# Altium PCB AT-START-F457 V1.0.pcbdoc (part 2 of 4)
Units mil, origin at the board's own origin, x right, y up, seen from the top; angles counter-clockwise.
Board outline 11593.57 x 3554 mil, 2 copper layers (Top Layer, Bottom Layer); 196 components, 231 nets, 905 pads, 932 vias.
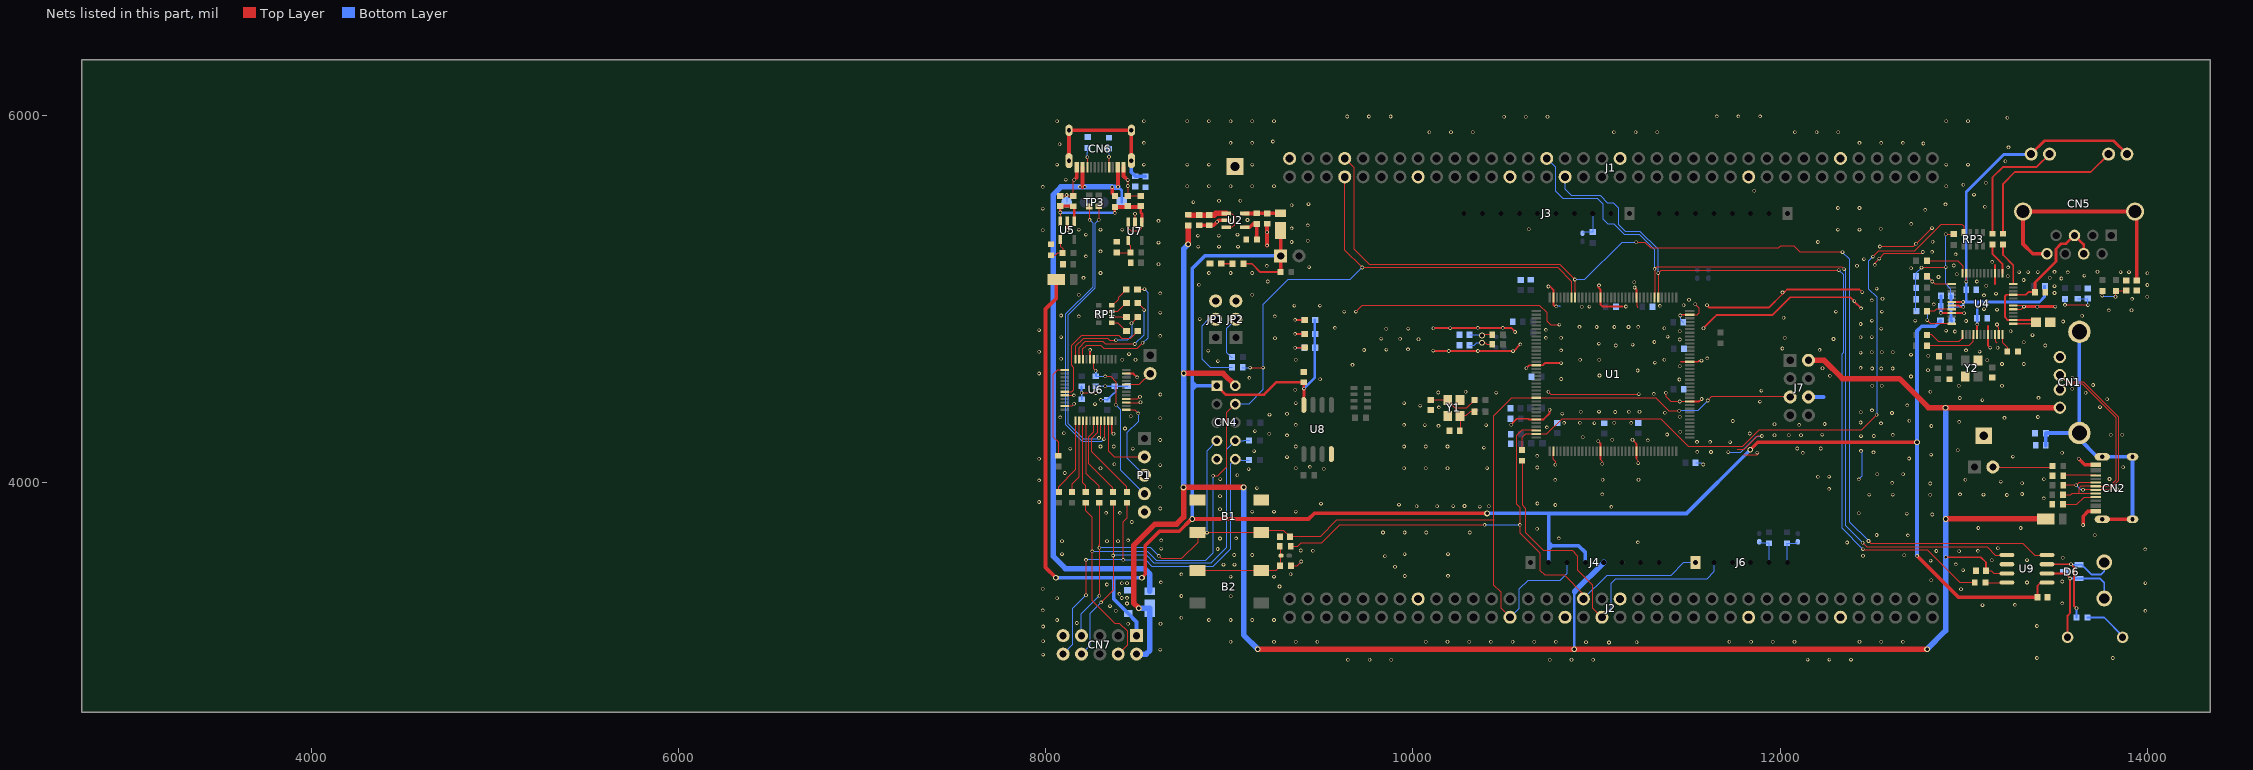
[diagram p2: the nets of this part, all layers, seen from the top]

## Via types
v1: diameter 19.7, hole 11.8, Top Layer to Bottom Layer, 489 vias
v2: diameter 19.68, hole 11.81, Top Layer to Bottom Layer, 425 vias
v3: diameter 31.5, hole 19.68, Top Layer to Bottom Layer, 18 vias

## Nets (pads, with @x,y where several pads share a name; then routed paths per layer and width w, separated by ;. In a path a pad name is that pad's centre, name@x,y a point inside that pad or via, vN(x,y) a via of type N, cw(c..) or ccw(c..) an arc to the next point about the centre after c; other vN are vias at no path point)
3V3: C13.1 C53.2 CN4.1 CN7.1 D1.1 D4.1 D5.1 J4.2 J4.4 JP3.1 L3.1 R10.1 R17.1 R26.1 R27.1 R28.1 U8.8 U9.5 | length 13515.4
  Top Layer w10: R10.1@9075.76,5191.98 9124.16,5191.98 9169.26,5146.98 R17.1@9280.76,5146.98 ; C53.2@13402.01,3375.61 13402.01,3438.05 13419.57,3455.61 U9.5@13453.72,3455.61
  Top Layer w15: CN4.1@8933.26,4527.98 8980.46,4480.48 9189.26,4479.18 9257.66,4547.38 9406.16,4547.38 9406.16,4512.98 9406.76,4512.38 U8.8@9406.16,4423.68
  Top Layer w20: v3(8056.02,3482.17) 7999.57,3538.62 7999.57,4945.41 8058.76,5004.61 D5.1@8058.76,5091.44 ; D5.1@8058.76,5107.05 D5.1@8058.76,5091.44 ; D5.1@8078.86,5111.53 D5.1@8058.76,5091.44 ; v3(8524.32,3482.61) 8542.32,3500.61 8542.32,3657.37 8620.57,3735.61 8728.41,3735.61 8794.76,3801.97 v3(8798.21,3801.97) 9432.21,3801.97 9462.85,3832.61 v3(10404.61,3832.61) ; D1.1@9280.21,5373.23 JP3.1@9280.21,5234.97 9280.16,5147.48 R17.1@9280.76,5146.98 ; v3(11837.81,4179.57) 11878.59,4220.35 v3(12745.71,4220.35) ; v2(12746.45,3600.9) 12971.74,3375.61 C53.2@13402.01,3375.61
  Bottom Layer w15: v2@9406.76,4512.38 9465.36,4571.08 R28.1@9465.36,4886.28
  Bottom Layer w20: v3(8056.02,3482.17) 8056.47,3482.61 8362.66,3482.61 ; CN7.1@8495.46,3166.58 8495.46,3241.74 D4.1@8449.57,3287.62 8370.57,3366.62 8370.57,3474.71 8362.66,3482.61 ; v3(8524.32,3482.61) 8362.66,3482.61 ; v3@8798.26,3801.98 8798.26,4505.87 ; CN4.1@8933.26,4527.98 8817.56,4528.58 ; JP3.1@9280.21,5234.97 8867.26,5234.98 8798.26,5165.98 8798.26,4547.88 ; v3(10404.61,3832.61) 10739.23,3832.61 10739.86,3831.98 ; J4.2@10739.86,3565.98 10739.86,3638.78 ; J4.4@10939.86,3565.98 10939.86,3619.38 10902.26,3656.98 10757.56,3656.98 ; v3(11837.81,4179.57) 11490.22,3831.98 10739.86,3831.98 ; v3(12745.71,4220.35) 12745.67,3601.69 v2(12746.45,3600.9) ; v3(12745.71,4220.35) 12745.67,4825.58 12771.76,4851.67 12844.53,4851.67 L3.1@12873.89,4881.03 ; 8798.26,4505.87 8817.56,4525.17 8817.56,4528.58 ; 8798.26,4505.87 8798.26,4547.88 ; 8798.26,4547.88 8817.56,4528.58 ; 10739.86,3638.78 10757.56,3656.98 ; 10739.86,3638.78 10739.86,3674.68 ; 10739.86,3674.68 10757.56,3656.98 ; 10739.86,3674.68 10739.86,3831.98
  other v2: 9406.72,4512.39
3V3_EMAC: C41.1 C42.1 C43.1 C44.1 CN5.9 CN5.12 L3.2 R66.1 R67.1 R68.1 R69.1 R72.2 R75.2 U4.23 U4.30 U4.31 U4.41 | length 3491.9
  Top Layer w6: v2(12770.45,5171.33) 12900.09,5171.33 v2(12902.68,5173.92) ; v2(12901.89,5353.19) 12944.44,5353.2 R68.1@12946.16,5351.48
  Top Layer w10: U4.30@12934.89,4983.81 12934.95,4983.87 v2(12996.99,4983.87) ; U4.31@12934.89,4964.13 12974.3,4964.13 12980.93,4957.51 v2(12997.27,4957.51) ; v2@13013.66,5094.98 U4.23@13013.66,5141.28 ; U4.41@13072.66,4806.68 13072.66,4860.98 v2@13073.76,4861.98
  Top Layer w15: CN5.12@13367.43,5789.39 13439.93,5861.97 13816.5,5861.97 CN5.9@13889.04,5789.42
  Bottom Layer w5.98: v2(12902.68,5173.92) 12902.68,5082.77 12930.86,5054.59 C42.1@12930.86,5017.89
  Bottom Layer w6: R72.2@12739.45,5122.7 12739.45,4937.91 R69.1@12742.21,4935.15 ; R72.2@12739.45,5124.27 12739.45,5140.34 v2(12770.45,5171.33) ; v2@12901.1,5352.36 12901.1,5175.49 v2(12902.68,5173.92)
  Bottom Layer w10: v2@13013.66,5094.98 v2@13013.76,5094.88
  Bottom Layer w15: C41.1@12930.22,4960.31 C41.1@12930.86,4960.31 ; C42.1@12930.86,5017.89 C41.1@12930.86,4960.31 ; L3.2@12934.52,4881.03 12930.86,4884.69 C41.1@12930.86,4960.31 ; v2(12997.27,4957.51) v2@12996.99,4957.78 ; v2@13073.76,4861.98 13073.76,4982.48 13072.26,4983.98 ; CN5.12@13367.43,5789.39 13364.96,5786.98 13218.26,5786.98 13013.76,5582.48 13013.76,5094.88 13013.76,4985.56 13015.44,4983.87 ; R75.2@13440.76,5069.98 13440.76,5012.48 13412.26,4983.98 13072.26,4983.98 ; C41.1@12930.86,4960.31 12994.46,4960.31 v2@12996.99,4957.78 ; v2@12996.99,4957.78 v2(12996.99,4983.87) 13015.44,4983.87 ; 13015.44,4983.87 13072.15,4983.87 13072.26,4983.98
  other v2: 13073.71,4861.97 13013.63,5094.97
5V: C52.2 CN1.1 CN4.2 CN7.2 D2.1 D3.1 F1.1 J4.5 J7.2 U9.3 | length 12164.3
  Top Layer w5.98: v3@12900.9,4408.11 v3(12901.18,4408.39) ; C52.2@13122.13,3520.61 13149.57,3520.61 13164.57,3505.61 U9.3@13235.42,3505.61
  Top Layer w10: v2(12902,3593.82) 13093.51,3593.82 13122.13,3565.2 C52.2@13122.13,3520.61
  Top Layer w30: v3(8507.66,3316.18) 8479.57,3344.27 8479.57,3658.61 8595.57,3774.61 8713.57,3774.61 8751.21,3812.25 v3(8751.21,3973.97) v3(9078.21,3973.97) ; v3(8752.21,4594.97) 8966.24,4594.97 CN4.2@9033.23,4527.98 ; v3@8776.26,5297.98 F1.1@8776.26,5399.98 ; v3(9155.76,3092.78) v3(10879.34,3092.78) v3(12800.59,3092.78) ; J7.2@12154.86,4666.58 12239.6,4666.58 12339.57,4566.61 12649.57,4566.61 12808.07,4408.11 12900.9,4408.11 CN1.1@13523.5,4408.11 ; v3(12902.7,3802.27) 12903.39,3802.96 D2.1@13445.99,3802.96
  Bottom Layer w15: v3(10879.34,3092.78) 10879.26,3092.87 10879.26,3404.98 10881.26,3406.98
  Bottom Layer w30: CN7.2@8495.46,3066.58 8547.53,3066.58 8567.57,3086.61 D3.1@8567.57,3315.86 8507.97,3315.86 v3(8507.66,3316.18) ; v3(8751.21,3973.97) 8751.21,5272.97 v3(8776.21,5297.97) ; v3@9078.26,3973.98 9078.26,3170.38 v3(9155.76,3092.78) ; 10881.26,3406.98 J4.5@11039.86,3565.98 ; v3(12800.59,3092.78) 12902.03,3194.21 v2(12902,3593.82) ; v3(12901.18,4408.39) 12902,4407.58 v2(12902,3593.82)
$2N452: C1.2 R1.1 Y1.1 | length 279.2
  Top Layer w6: C1.2@10097.57,4450.17 10097.82,4449.92 Y1.1@10190.1,4449.92 10190.1,4445.99 10231.48,4404.61 10291.04,4404.61 10335.91,4449.48 R1.1@10335.91,4450.61
$2N453: C2.2 R3.1 Y1.3 | length 170
  Top Layer w6: C2.2@10255.13,4282.61 10257.03,4284.52 Y1.3@10257.03,4363.3 10288.26,4363.3 10311.57,4386.61 R3.1@10335.91,4386.61
$2N511: C3.2 R5.1 X1.1 | length 127.4
  Top Layer w5.98: X1.1@10376.57,4801.3 10381.19,4805.92 R5.1@10432.54,4805.92
  Bottom Layer w5.98: C3.2@10308.62,4805.16 10372.7,4805.16 X1.1@10376.57,4801.3
$2N512: C4.2 R6.1 X1.2 | length 132.6
  Top Layer w5.98: X1.2@10376.57,4761.93 10394.24,4761.93 10402.99,4753.19 R6.1@10432.54,4753.19
  Bottom Layer w5.98: C4.2@10308.63,4749.61 10335.57,4749.61 10347.88,4761.93 X1.2@10376.57,4761.93
$2N701: JP1.2 R13.1 | length 455.4
  Bottom Layer w6: JP1.2@8926.26,4889.98 8887.16,4889.98 8850.26,4852.98 8850.26,4674.98 8897.16,4627.98 R13.1@9016.76,4627.98
$2N702: JP2.2 R14.1 | length 244.9
  Bottom Layer w6: R14.1@9017.76,4683.98 9011.76,4683.98 8984.26,4711.48 8984.26,4837.98 JP2.2@9036.26,4889.98
$3N58: C5.1 C6.1 F1.2 U2.1 U2.3 | length 369.5
  Top Layer w6: U2.1@8971.16,5465.98 9014.56,5464.58 9026.26,5452.98 9026.26,5402.98 9014.16,5390.98 U2.3@8984.26,5390.98
  Top Layer w30: F1.2@8776.26,5459.28 8778.36,5457.08 8836.21,5457.08 8891.21,5457.08 8917.86,5457.08 8926.66,5465.98 8971.16,5465.98 U2.1@8984.26,5465.98
$3N81: R15.1 R16.1 U2.4 | length 160.8
  Top Layer w20: U2.4@9084.26,5390.98 9111.16,5390.98 9130.76,5410.48 9150.26,5410.48 9150.26,5324.48 R15.1@9149.66,5323.98
$3N82: C7.1 D1.2 R16.2 U2.5 | length 196.6
  Top Layer w20: U2.5@9084.26,5465.98 9114.76,5465.98 9115.16,5465.48 9150.16,5465.48 9151.46,5466.68 D1.2@9280.21,5466.73
$3N119: LED1.1 R10.2 | length 64.5
  Top Layer w10: LED1.1@8956.26,5192.78 R10.2@9020.76,5191.98
$3N184: B2.2 B2.4 R18.2 R19.1 R20.1 | length 568
  Top Layer w6: B2.4@8828.03,3521.56 B2.2@9174.49,3521.56 9252.26,3521.58 9278.66,3547.98 9277.66,3548.98 R19.1@9277.66,3653.98
$3N504: LED2.1 R26.2 | length 104.4
  Top Layer w10: v2@9358.66,4734.58 9359.26,4735.18 LED2.1@9411.01,4735.2
  Bottom Layer w10: v2@9358.66,4734.58 9359.06,4734.98 R26.2@9410.36,4734.98
  other v2: 9358.65,4734.61
$3N505: LED3.1 R27.2 | length 104.1
  Top Layer w10: v2@9358.66,4809.98 LED3.1@9411.06,4810.18
  Bottom Layer w10: v2@9358.66,4809.98 R27.2@9410.36,4809.98
  other v2: 9358.65,4810
$3N506: LED4.1 R28.2 | length 104.1
  Top Layer w10: v2@9358.66,4886.28 LED4.1@9411.06,4886.48
  Bottom Layer w10: v2@9358.66,4886.28 R28.2@9410.36,4886.28
  other v2: 9358.65,4886.3
$3N17443: CN2.B5 R33.2 | length 177
  Top Layer w5.98: R33.2@13542.43,4038.23 13543.84,4039.63 CN2.B5@13718.81,4039.63
$3N17484: CN2.A5 R32.2 | length 193.6
  Top Layer w5.98: R32.2@13541.65,3881.81 13615.76,3881.81 13655.49,3921.53 CN2.A5@13718.81,3921.53
$3N17593: JP4.2 R34.1 | length 326.5
  Top Layer w5.98: JP4.2@13158.9,4085.21 13477.69,4085.21 R34.1@13483.11,4090.63
$3N21099: R90.2 U9.4 | length 116.2
  Top Layer w5.98: R90.2@13119.23,3455.61 U9.4@13235.42,3455.61
$3N21100: R89.1 SW1.2 | length 240.3
  Bottom Layer w10: R89.1@13674.23,3265.61 13764.57,3265.61 13865.56,3164.62 SW1.2@13865.56,3157.52
$4N269: J6.5 R56.2 R57.2 | length 163
  Bottom Layer w6: R56.2@11886.26,3678.68 11892.46,3672.48 11940.16,3672.48 J6.5@11939.86,3565.98
$4N270: J6.6 R58.2 R59.2 | length 168.5
  Bottom Layer w6: J6.6@12039.8,3565.97 12039.81,3667.56 R59.2@12037.06,3670.3 12089.36,3670.3 R58.2@12096.95,3677.89
$4N339: J3.3 R60.1 R61.2 | length 161.8
  Bottom Layer w6: R60.1@10926.16,5357.28 10926.16,5362.48 10979.26,5362.48 J3.3@10979.86,5465.98
$5N126: R62.2 U4.24 | length 246.2
  Top Layer w6: R62.2@12799.87,5209.08 12967.15,5209.08 12993.96,5182.28 U4.24@12993.96,5141.28
$5N184: R69.2 U4.36 | length 191
  Top Layer w6: v2(12801.82,4885.52) 12821.66,4865.68 U4.36@12934.89,4865.7
  Bottom Layer w6: R69.2@12801.53,4935.15 12801.82,4934.86 v2(12801.82,4885.52)
$5N285: C46.1 R76.1 R77.1 | length 250.4
  Top Layer w6: v2(13551.96,4968) 13552.87,4967.09 v2(13676.61,4967.09)
  Bottom Layer w5.98: R77.1@13621.73,5001.24 13675.18,5001.24 C46.1@13676.49,5002.55 13676.61,5002.44 v2(13676.61,4967.09)
  Bottom Layer w6: v2(13551.96,4968) 13551.96,5002.28 R76.1@13552.16,5002.48
$5N306: C47.1 R78.1 R79.1 | length 189.5
  Top Layer w6: v2(13754.72,5018.4) R78.1@13754.72,5043.84 ; v2(13826.57,5012.57) 13827,5013 13827,5043.18 13830.21,5046.39 C47.1@13884.55,5046.39
  Bottom Layer w6: v2(13754.72,5018.4) 13760.72,5012.4 13826.4,5012.4 v2(13826.57,5012.57)
$5N309: CN5.10 R80.1 | length 915.5
  Top Layer w10: R80.1@13214.26,5353.48 13214.26,5626.98 13279.26,5691.98 13691.56,5691.98 CN5.10@13789.09,5789.39
$5N310: CN5.11 R81.1 | length 672.4
  Top Layer w10: R81.1@13156.26,5353.48 13156.26,5661.98 13214.26,5719.98 13397.96,5719.98 CN5.11@13467.43,5789.39
$5N573: R74.2 U4.48 | length 103.9
  Top Layer w6: U4.48@13210.46,4806.68 13210.46,4764.93 13237.11,4738.27 R74.2@13237.11,4713.81
$6N792: LD1.1 RP1.8 | length 121.7
  Top Layer w6: RP1.8@8360.2,4965.45 8363.16,4965.45 8397.25,4999.55 8397.25,5009.62 8439.43,5051.8 LD1.1@8439.43,5052.63
$6N793: LD2.1 RP1.7 | length 98.6
  Top Layer w6: RP1.7@8360.2,4933.96 8393.82,4933.96 8438.39,4978.53 LD2.1@8440.39,4978.53
$6N794: LD3.1 RP1.6 | length 80.6
  Top Layer w6: RP1.6@8360.2,4902.46 8415.6,4902.46 8416.43,4901.63 LD3.1@8440.43,4901.63
$6N795: LD4.1 RP1.5 | length 99
  Top Layer w6: RP1.5@8360.2,4870.97 8393.05,4870.97 8438.39,4825.63 LD4.1@8440.39,4825.63
$6N16959: C15.2 C16.2 C18.2 C19.2 F2.2 U5.1 U5.3 U7.1 U7.3 | length 955.4
  Top Layer w6: v2(8079.97,5471.01) 8079.97,5424.64 U5.3@8080.56,5424.05 ; U7.3@8449.34,5418.39 8449.34,5386.85 8465.17,5371.01 8510.77,5371.01 8524.34,5384.58 U7.1@8524.34,5418.39
  Top Layer w15: v2(8079.97,5471.01) 8079.97,5504.25 8077.97,5506.25 8149.57,5506.25 C19.2@8150.37,5505.45 8155.56,5500.26 U5.1@8155.56,5424.05 ; v2(8376.76,5469.02) 8376.76,5500.59 F2.2@8377.56,5501.39 ; C16.2@8517.56,5506.49 8517.56,5471.42 8524.34,5464.65 U7.1@8524.34,5418.39
  Top Layer w20: F2.2@8377.56,5501.39 8512.46,5501.39 C16.2@8517.56,5506.49
  Bottom Layer w15: v2(8079.97,5471.01) 8081.17,5469.81 8375.97,5469.81 v2(8376.76,5469.02)
$6N17598: R43.2 R49.1 U7.4 | length 144.7
  Top Layer w6: R49.1@8387.57,5252.95 8439.57,5252.95 8440.03,5253.41 R43.2@8461.9,5253.41 8461.9,5290.28 8449.34,5302.85 U7.4@8449.34,5318.39
$6N17675: R50.2 R51.1 U5.4 | length 146.5
  Top Layer w6: R51.1@8029.57,5238.95 8052.89,5238.95 8064.98,5251.05 R50.2@8092.9,5251.05 8092.9,5275.68 8080.56,5288.02 U5.4@8080.56,5324.05
ATLINK_5V: CN6.A4B9 CN6.B4A9 D3.2 F2.1 TP3.1 | length 3362.8
  Top Layer w20: CN6.B4A9@8200.71,5717.9 8200.71,5609.88 8201.17,5609.41 ; v2(8362.76,5609.37) 8362.76,5575.52 F2.1@8377.56,5560.71 ; CN6.A4B9@8393.71,5717.9 8394.27,5717.34 v2(8394.27,5611.13)
  Bottom Layer w15: v2(8394.27,5611.13) 8414.58,5590.82 TP3.1@8414.58,5526.61
  Bottom Layer w30: v2(8394.27,5611.13) 8392.51,5609.37 v2(8362.76,5609.37) 8361.51,5610.61 v2(8213.24,5610.61) v2(8186.47,5610.61) 8083.57,5610.61 8042.25,5569.3 8042.25,3597.93 8108.3,3531.88 8537.57,3531.88 8567.57,3501.88 D3.2@8567.57,3409.36
ATLK_BOOT0: R45.1 U6.27 | length 395.7
  Top Layer w6: U6.27@8203.01,4337.98 8202.96,3998.78 8218.46,3983.38 R45.1@8218.46,3948.68
ATLK_NRST: R46.1 U6.28 | length 419.2
  Top Layer w6: U6.28@8222.69,4337.98 8222.66,4049.48 8292.46,3979.78 R46.1@8292.46,3947.68
ATLK_RX: CN4.10 CN7.10 R25.1 R48.2 | length 2281.5
  Top Layer w6: v2(8219.86,3386.38) 8219.86,3578.78 v2(8220.26,3579.18) ; v2@8425.16,3576.68 v2(8422.66,3579.18) 8422.66,3788.08 8443.66,3809.08 R48.2@8443.66,3892.68
  Bottom Layer w6: CN7.10@8095.46,3066.58 8145.96,3117.18 8145.96,3312.48 v2(8219.86,3386.38) ; v2(8220.26,3579.18) v2(8422.66,3579.18) 8545,3579.18 8579.46,3544.73 8913.43,3544.73 9007.59,3638.89 9007.59,4102.34 CN4.10@9033.23,4127.98 ; CN4.10@9061.16,4128.18 9066.16,4123.08 R25.1@9110.16,4123.08
ATLK_SWCLK: R41.1 U6.25 | length 427
  Top Layer w6: R41.1@8070.46,3949.58 8070.46,3979.08 8163.66,4072.28 U6.25@8163.66,4337.98
ATLK_SWDIO: R44.1 U6.26 | length 404.5
  Top Layer w6: R44.1@8144.46,3949.58 8144.46,3993.08 8183.36,4031.98 U6.26@8183.36,4337.98
ATLK_SWO: R52.1 U6.13 | length 530.4
  Top Layer w6: R52.1@8070.26,4142.58 8070.26,4218.73 8042.65,4246.34 8042.65,4589.69 8066.53,4613.58 U6.13@8104.58,4613.57
ATLK_TX: CN4.8 CN7.8 R24.1 R47.2 | length 2247.2
  Top Layer w6: v2(8302.46,3348.18) 8367.5,3413.22 v2(8367.5,3603.41) 8367.5,3846.62 8367.66,3846.78 R47.2@8367.66,3892.68
  Bottom Layer w6: CN7.8@8195.43,3066.63 8244,3115.2 8244,3289.72 v2(8302.46,3348.18) ; v2(8367.5,3603.41) 8368.11,3604.03 8550.15,3604.03 8592.12,3562.06 8900.43,3562.06 8985.14,3646.77 8985.14,4179.88 CN4.8@9033.23,4227.98 ; CN4.8@9033.26,4227.98 9078.86,4227.98 9080.96,4229.98 R24.1@9110.76,4229.98
AVDD18: C45.2 C48.2 CN5.4 CN5.5 U4.1 U4.2 U4.9 | length 1127.8
  Top Layer w10: U4.1@13269.53,4865.7 13384.64,4865.7 C45.2@13393.08,4874.14 13381.83,4885.39 U4.2@13269.53,4885.39 13240.46,4885.38 13225.36,4900.48 13225.36,5016.28 13232.26,5023.18 13269.56,5023.18 13337.46,5023.18 13352.26,5037.98 C48.2@13388.65,5037.97
  Top Layer w15: C48.2@13388.65,5037.97 13388.66,5090.48 13502.76,5204.58 13502.76,5273.18 13531.16,5301.58 13558.26,5301.58 13603.26,5346.48 13653.26,5296.48 CN5.4@13653.26,5246.48
BOOT0: CN4.4 CN7.4 J1.66 R13.2 R45.2 U1.138 | length 5702.5
  Top Layer w6: R45.2@8218.66,3892.68 8218.66,3846.33 8253.97,3811.01 8253.97,3355.87 8378.26,3231.58 8403.96,3231.58 8446.06,3189.58 8446.06,3117.18 CN7.4@8395.46,3066.58 ; v2(8912.21,4037.97) 8937.81,4037.97 8987.5,4087.66 8987.5,4382.24 CN4.4@9033.23,4427.98 ; v2(9113.66,4626.6) v2(9184.53,4626.6) ; J1.66@9629.16,5665.18 9629.16,5266.98 v2(9724.26,5171.98) 10789.04,5171.98 10863.86,5097.17 U1.138@10863.86,5008.28
  Bottom Layer w6: v2(8254.21,3625.97) 8554.21,3625.97 8603.22,3576.97 8870.92,3576.97 8912.21,3618.25 v2(8912.21,4037.97) ; CN4.4@9033.26,4427.98 9105.76,4428.18 9183.26,4505.68 9183.26,4968.98 9319.14,5104.86 9657.14,5104.86 v2(9724.26,5171.98) ; R13.2@9071.76,4627.98 9073.06,4626.58 v2(9113.66,4626.6)
CAN1_RX: J1.42 R90.1 U1.114 | length 4279.4
  Top Layer w5.98: v2(11336.13,5141.22) 11352.2,5157.28 v1(12319.64,5157.28) ; v2(12451.03,3638.03) 12456.31,3632.75 12804.57,3632.75 12981.7,3455.61 R90.1@13059.91,3455.61
  Top Layer w6: v2(11336.13,5141.22) 11336.08,5008.45 U1.114@11336.26,5008.28
  Bottom Layer w5.98: v1(12319.64,5157.28) 12342.85,5134.07 12342.85,4706.82 12335.71,4699.68 12335.71,3753.35 v2(12451.03,3638.03)
  Bottom Layer w6: J1.42@10829.16,5665.68 10829.16,5596.98 10864.26,5561.98 11022.26,5561.98 11062.16,5521.98 11094.26,5521.98 11122.26,5493.98 11122.26,5404.58 11160.26,5366.58 11239.56,5366.58 11336.08,5270.05 v2(11336.13,5141.22)
CAN1_STB: J1.65 U1.137 U9.8 | length 6093.1
  Top Layer w5.98: v2(11216.97,5309.63) 11264.09,5309.63 11295.07,5278.65 11993.09,5278.65 12004.09,5289.66 12073.68,5289.66 12106.14,5257.2 12338.43,5257.2 v2(12339.88,5255.76) ; v2(12481.84,3682.37) 12494.32,3669.89 13321.46,3669.89 13385.74,3605.61 U9.8@13453.72,3605.61
  Top Layer w6: J1.65@9629.16,5765.68 9680.26,5714.58 9680.26,5271.88 9766.26,5185.98 10803.15,5185.98 v2(10882.68,5106.45) 10883.56,5105.57 U1.137@10883.56,5008.28
  Bottom Layer w5.98: v2(10882.68,5106.45) 10936.81,5106.45 11139.99,5309.63 v2(11216.97,5309.63) ; v2(12339.88,5255.76) 12378.61,5217.03 12378.61,3785.6 v2(12481.84,3682.37)
CAN1_TX: J1.43 U1.115 U9.1 | length 4566.6
  Top Layer w5.98: v2(11316.43,5164.07) 11328.47,5176.1 12335.64,5176.1 v2(12348.76,5162.99) ; v2(12449.79,3672.41) 12471.81,3650.38 13128.09,3650.38 13172.86,3605.61 U9.1@13235.42,3605.61
  Top Layer w6: v2(11316.43,5164.07) 11316.38,5008.45 U1.115@11316.56,5008.28
  Bottom Layer w6: J1.43@10729.16,5765.68 10778.26,5716.58 10778.26,5585.88 10818.26,5545.98 11006.26,5545.98 11036.26,5515.98 11036.26,5433.88 11063.76,5406.38 11095.86,5406.38 11153.26,5348.98 11235.96,5348.98 11316.38,5268.55 v2(11316.43,5164.07) ; v2(12348.76,5162.99) 12356.62,5155.12 12356.62,3765.58 v2(12449.79,3672.41)
CAN_H: CN8.2 D6.1 R89.2 U9.7 | length 693.4
  Top Layer w10: U9.7@13453.72,3555.61 v2(13584.57,3555.61) 13600.4,3539.79 13600.4,3329.79 v2(13614.57,3315.61)
  Bottom Layer w10: v2(13584.57,3555.61) 13587.17,3553.01 D6.1@13628.94,3553.01 13642.17,3553.01 13694.57,3500.61 13749.57,3500.61 13765.59,3516.64 CN8.2@13765.59,3566.16 ; v2(13614.57,3315.61) 13614.57,3265.95 R89.2@13614.91,3265.61
CAN_L: CN8.1 D6.2 SW1.1 U9.6 | length 744.8
  Top Layer w10: U9.6@13453.72,3505.61 13552.17,3505.61 v2(13579.57,3478.21) 13579.57,3290.14 13565.56,3276.13 SW1.1@13565.56,3157.52
  Bottom Layer w10: v2(13579.57,3478.21) D6.2@13628.94,3478.21 13741.97,3478.21 13765.59,3454.59 CN8.1@13765.59,3369.31
CC1: CN6.A5 R86.1 | length 101.4
  Top Layer w6: v1(8345.57,5774.61) 8346.41,5773.78 CN6.A5@8346.41,5717.9
  Bottom Layer w6: v1(8345.57,5774.61) R86.1@8345.57,5818.95
CC2: CN6.B5 R87.1 | length 106.2
  Top Layer w6: v1(8227.57,5772.61) 8228.31,5771.88 CN6.B5@8228.31,5717.9
  Bottom Layer w6: v1(8227.57,5772.61) 8227.57,5799.08 8229.57,5801.08 R87.1@8229.57,5822.95
CRS_DV: R70.2 U4.37 | length 239.5
  Top Layer w6: R70.2@12798.36,4804.28 12826.26,4804.28 12864.5,4766.13 12972.68,4766.13 12993.96,4787.4 U4.37@12993.96,4806.68
EGND: C20.2 CN6.13 CN6.14 CN6.15 CN6.16 R88.1 | length 818.4
  Top Layer w20: CN6.14@8127.11,5753.9 CN6.16@8127.11,5918.5 CN6.15@8467.31,5918.5 CN6.13@8467.31,5753.9
  Bottom Layer w20: CN6.13@8467.31,5753.9 8467.31,5690.44 C20.2@8489.57,5668.17 8543.47,5668.17 R88.1@8543.57,5668.27
EGND1: C21.1 CN1.SH1 CN1.SH2 CN2.13 CN2.14 CN2.15 CN2.16 R35.2 | length 1667.6
  Top Layer w20: CN2.13@13754.81,3800.63 CN2.15@13919.41,3800.63
  Bottom Layer w20: C21.1@13447.12,4202.84 13447.39,4203.11 R35.2@13447.39,4268.59 13449.12,4270.32 CN1.SH2@13630.19,4270.32 ; CN1.SH1@13630.19,4821.51 CN1.SH2@13630.19,4270.32 ; CN2.15@13919.41,3800.63 CN2.16@13919.41,4140.83 CN2.14@13754.81,4140.83 13726.53,4140.83 13630.19,4237.17 CN1.SH2@13630.19,4270.32
EMAC_GND: C49.2 CN5.8 CN5.SH1 CN5.SH2 | length 1317
  Top Layer w20: CN5.8@13453.21,5246.51 13376.67,5246.51 13323.29,5299.89 CN5.SH2@13323.34,5476.4 CN5.SH1@13933.13,5476.43 ; CN5.SH1@13933.16,5476.48 13941.66,5467.98 C49.2@13941.66,5101.4
EMAC_NRST: R71.2 U4.40 | length 296
  Top Layer w6: R71.2@12804.9,4753.13 12810.62,4747.41 13029.57,4747.41 13052.96,4770.8 U4.40@13052.96,4806.68
GND: B1.2 B1.4 C1.1 C2.1 C3.1 C4.1 C5.2 C6.2 C7.2 C8.1 C9.1 C10.1 C11.1 C12.1 C13.2 C14.1 C15.1 C16.1 C17.1 C18.1 C19.1 C20.1 C21.2 C22.1 C23.2 C24.2 C25.2 C26.2 C27.2 C28.2 C29.2 C30.2 C31.2 C32.2 C33.2 C34.2 C35.2 C36.2 C37.2 C38.2 C39.2 C40.2 C41.2 C42.2 C43.2 C44.2 C45.1 C46.2 C47.2 C48.1 C49.1 C50.2 C51.2 C52.1 C53.1 CN1.4 CN2.A1B12 CN2.B1A12 CN4.9 CN6.A1B12 CN6.B1A12 CN7.9 D4.2 D6.3 J1.11 J1.22 J1.35 J1.48 J1.58 J1.71 J2.16 J2.31 J2.38 J2.51 J2.61 J3.7 J4.6 J4.7 J7.6 JP1.3 JP2.3 LED1.2 P1.5 R15.2 R18.1 R32.1 R33.1 R35.1 R49.2 R51.2 R74.1 R82.2 R86.2 R87.2 R88.2 T1.1 T2.1 TP3.4 U1.16 U1.31 U1.38 U1.51 U1.61 U1.83 U1.94 U1.107 U1.120 U1.130 U1.143 U2.2 U4.5 U4.6 U4.15 U4.33 U4.44 U4.46 U4.47 U5.2 U6.8 U6.20 U6.23 U6.35 U6.39 U6.40 U6.47 U7.2 U8.4 U9.2 Y1.2 Y1.4 Y2.2 Y2.4 | length 10772.5
  Top Layer w5.98: v1(9689.57,4931.61) 9725.42,4967.46 10643.09,4967.46 ; v1(10738.1,4495.53) 10751.39,4482.25 v2(11229.94,4482.25) ; U1.120@11218.12,5008.31 11218.12,4964.07 11225.57,4956.61 ; v2(11377.86,4489.56) 11377.86,4470.02 11405.58,4442.3 v1(11453.48,4442.3) ; U1.107@11508.48,4914.79 11549.27,4914.79 ; 11767.83,4180.05 11801.78,4180.05 11875.75,4254.02 v2(11901.18,4254.02) ; 11799.38,4156.06 11802.16,4153.28 11875.4,4153.28 11886.93,4164.81 ; v2(12515.24,5185.87) 12515.24,5195 v2(12540.24,5220) 12565.9,5245.66 12766.81,5245.66 v1(12777.31,5256.16) ; v2(12543.6,5285.84) 12724.31,5285.84 v2(12739.69,5301.22) 12742.32,5301.22 v2(12827.11,5386.01)
  Top Layer w6: C18.1@8080.37,5561.37 8149.57,5561.37 C19.1@8150.37,5560.57 8150.37,5644.21 v2(8156.11,5649.96) ; U6.23@8104.58,4416.72 8142.48,4416.72 v2(8155.17,4429.41) ; U6.20@8104.58,4475.78 8153.2,4475.78 v2(8153.97,4475.01) ; v2(8196.37,4489.41) 8197.17,4488.61 8272.57,4488.61 v2(8273.57,4487.61) ; U6.39@8439.23,4436.41 8515.15,4436.41 v2(8516.94,4438.2) ; U6.40@8439.23,4456.09 8501.93,4456.09 v2(8514.03,4468.19) ; v2(8447.17,5647.41) v1(8447.17,5615.61) 8447.17,5584.75 8448.56,5583.36 C15.1@8448.56,5561.61 C16.1@8517.56,5561.61 ; v2(8487.17,5464.21) 8487.34,5464.05 U7.2@8487.34,5418.39 ; R18.1@9335.87,3547.97 9369.42,3547.97 v1(9391.96,3570.51) ; 10643.09,4967.46 10689.19,4967.46 10729.37,4927.27 10729.37,4882.17 10750.75,4860.8 v1(10798.05,4860.8) ; U1.38@10765.46,4171.68 10765.46,4128.38 10776.57,4117.27 v1(10776.57,4097.61) ; U1.51@11021.36,4171.68 11021.36,4127.78 11031.5,4117.74 ; v1(11031.57,4102.61) 11031.57,4117.67 ; 11218.16,4134.08 11218.16,4127.28 11227.57,4117.87 v1(11227.57,4106.61) ; v1(11453.48,4442.3) U1.83@11508.48,4442.35 ; v1(11538.13,4971.64) 11558.57,4951.2 11558.57,4924.09 11549.27,4914.79 ; U4.46@13171.11,4806.65 13171.11,4770.74 13181.24,4760.61 ; v1@13182.03,4852.02 13190.79,4843.26 U4.47@13190.79,4806.65 ; U4.5@13269.56,4944.48 13313.74,4944.48 v1(13328.27,4959.02) 13323.21,4964.08 U4.6@13269.56,4964.08
  Top Layer w8: v1(12404.47,4988.61) 12404.47,4986.01 v2(12441.4,4949.08)
  Top Layer w10: U6.8@8242.36,4672.68 8242.43,4672.75 v2(8242.43,4723.22) ; U6.35@8360.49,4337.98 8360.49,4275.35 v2(8369.66,4266.18) ; U6.47@8439.26,4593.88 8478.39,4594.19 v2(8499.17,4573.41) ; v1(10110.79,4718.95) 10113.32,4716.42 v1@10354.83,4716.42 ; v1(10111.81,4841.3) 10113.15,4842.65 v1(10353.84,4842.64) v1(10490,4842.65) 10534.96,4842.65 v1(10556.84,4820.77) ; v1(10354.19,4717.06) v1@10354.83,4716.42 ; v1@10538.26,4321.28 10565.16,4348.18 10628.39,4348.18 10632.7,4343.88 U1.31@10671.86,4343.93 10711.26,4343.88 10744.91,4377.54 v1(10744.91,4396.83) ; v1(10585.97,4753.15) 10549.24,4716.42 v1(10545.41,4716.42) v1@10354.83,4716.42 ; v2(10618.26,4623.08) 10634.36,4639.18 U1.16@10671.86,4639.2 10708.16,4639.18 10721.56,4652.58 10806.07,4652.58 v1(10807.75,4650.9) ; v1(10738.21,5068.19) 10747.36,5068.19 10765.36,5050.18 U1.143@10765.37,5008.31 10765.36,4968.98 v1@10772.76,4961.68 ; v1(11009.57,4225.61) 11021.26,4213.93 U1.51@11021.27,4171.68 11021.26,4129.48 ; v1@11011.86,5076.32 11011.86,5061.58 11021.36,5052.18 11021.36,5008.31 11021.36,4972.08 11034.26,4959.18 11143.06,4959.18 ; v1(11196.57,4233.61) 11218.16,4212.03 11218.16,4171.68 11218.16,4134.08 ; v1@11214.76,5056.08 11218.16,5052.78 U1.120@11218.16,5008.31 ; v1(11456.57,4910.61) 11456.57,4914.78 U1.107@11508.48,4914.79 ; 11460.26,4658.88 U1.94@11508.48,4658.89 11553.16,4658.88 11557.56,4663.28 ; U1.83@11508.56,4442.28 11559.66,4442.28 v1(11572.76,4455.38) ; v2(11582.78,4840.92) 11639.04,4897.19 11639.04,4897.57 11653.8,4912.32 11956.96,4912.32 12054.33,5009.69 12383.39,5009.69 v1(12404.47,4988.61) ; v2(11602.21,4966.3) 11615.21,4953.3 11939.11,4953.3 12013.26,5027.45 v2(12013.26,5036.37) 12022.17,5036.37 12037.85,5052.04 12432.69,5052.04 v1(12447.28,5037.46) ; v1(12875.29,4924.46) 12992.54,4924.46 v1@12992.86,4924.78 ; 13131.76,4854.78 13131.76,4806.68 13131.76,4747.84 v1(13144.2,4735.4) ; 13171.16,5082.48 13171.16,5141.28 13171.16,5185.38
  Top Layer w15: U5.2@8118.56,5424.05 8119.17,5423.44 v2(8119.17,5375.81) ; v1(13328.27,4959.02) v1@13401.91,4959.02 ; v1(13400.7,4957.81) v1@13401.91,4959.02 ; v2(13499.02,4959.02) v1@13401.91,4959.02
  Top Layer w20: v2(8156.11,5649.96) 8170.41,5664.25 CN6.B1A12@8170.41,5717.9 ; CN6.A1B12@8424.21,5717.9 8424.21,5670.38 v2(8447.17,5647.41) ; C5.2@8836.21,5402.05 C6.2@8891.21,5402.05 8915.36,5402.08 v1(8934.33,5421.12) 8942.16,5428.98 U2.2@8984.26,5428.98 ; C7.2@9206.16,5410.48 v1(9206.16,5364.21) v1(9206.16,5291.98) v1@9206.26,5291.98 ; v1(13626.21,4130.4) 13659.08,4097.53 CN2.B1A12@13718.81,4097.53 ; v2(13650.43,3769.56) 13650.43,3817.62 13676.54,3843.73 CN2.A1B12@13718.81,3843.73
  Bottom Layer w5.98: C29.2@11539.56,4109.02 11571.61,4109.02 v2(11581.86,4098.76) ; v1(11717.47,4166.43) 11784.75,4166.43 11872.35,4254.02 v2(11901.18,4254.02) ; 12415.86,4976.04 12441.4,4950.5 v2(12441.4,4949.08) ; v2(12428.36,4018.07) 12446.11,4035.81 12446.11,4167.22 v2(12440.44,4172.88)
  Bottom Layer w6: TP3.4@8114.58,5526.61 v1(8114.57,5566.61) ; v2(8273.57,4487.61) 8273.97,4488.01 C22.1@8273.97,4524.65 ; v2(8300.41,4450.97) C11.1@8335.17,4450.97 ; v1(10781.23,4959.9) 10802.13,4959.9 10802.77,4959.26 ; v1(11456.57,4910.61) 11456.57,4889.17 C32.2@11473.13,4872.61
  Bottom Layer w10: C12.1@8196.37,4524.65 v2(8196.37,4489.41) 8196.77,4489.01 C10.1@8196.77,4453.77 ; C22.1@8273.97,4524.65 v2(8325.27,4524.65) C9.1@8376.37,4524.65 ; C11.1@8335.17,4450.97 8371.21,4487.01 8375.17,4487.01 8382.24,4494.09 8382.24,4504.09 8376.37,4509.96 C9.1@8376.37,4524.65 ; C9.1@8376.37,4525.05 C9.1@8376.37,4524.65 ; C8.1@8446.37,4525.85 8418.65,4525.85 8417.45,4524.65 C9.1@8376.37,4524.65
  Bottom Layer w15: v1(12875.29,4924.46) 12875.74,4924.91 C42.2@12875.74,5017.89
  Bottom Layer w20: J7.6@12154.81,4466.56 12237.88,4466.56
  other v1: 9646.44,3035.82 9764.55,3035.82 9882.66,3035.82 10745.74,3035.82 10863.85,3035.82 10981.96,3035.82 12150.21,3036.6 12268.32,3036.6 12386.43,3036.6 7986.57,3063.61 8624.57,3090.61 11068.29,3129.68 10942.92,3130.71 11218.56,3130.71 9007.66,3133.82 9243.88,3133.82 9361.99,3133.82 9480.1,3133.82 10070.65,3133.82 10188.76,3133.82 10306.87,3133.82 10424.98,3133.82 10543.09,3133.82 10661.2,3133.82 10779.31,3133.82 11724.2,3133.82 11842.31,3133.82 11960.42,3133.82 12078.53,3133.82 12432.86,3133.82 12550.97,3133.82 12669.08,3133.82 7986.57,3136.61 7986.57,3216.61 8449.57,3231.61 8625.57,3231.61 8169.57,3235.61 8062.78,3251.94 8889.55,3251.94 9007.66,3251.94 9125.77,3251.94 9243.88,3251.94 8739.57,3264.39 8382.07,3302.11 7984.57,3304.39 8350.57,3327.61 8443.57,3341.61 8062.78,3370.05 8415.07,3372.14 8443.57,3372.61 9008.57,3381.61 8739.57,3382.5 8402,3394.41 7984.57,3422.5 9273.57,3434.61 8333.57,3445.61 8415.57,3452.61 8443.57,3452.61 8627.57,3456.61 9007.66,3488.16 9243.88,3488.16 9955.57,3491.61 10191.55,3492.51 8739.57,3500.61 9334.55,3501.51 9902.57,3541.61 8968.57,3553.61 9028.57,3553.61 9847.57,3599.61 9027.66,3606.27 9125.77,3606.27 8089.57,3610.61 9955.33,3610.62 10191.55,3610.62 9455.57,3629.61 9389.57,3630.61 8936.59,3638.67 8629.57,3640.61 8089.57,3680.61 8334.57,3680.61 8394.57,3680.61 8449.57,3685.61 8629.57,3685.61 8949.57,3695.61 9037.57,3696.61 9837.22,3728.73 9955.33,3728.73 10073.44,3728.73 10309.66,3728.73 8469.57,3785.61 8329.57,3835.61 8404.57,3835.61 9125.77,3842.49 9243.88,3842.49 9361.99,3842.49 8949.57,3855.61 8624.57,3859.39 10364.44,3869.4 10020.63,3871.48 10413.41,3871.32 10131.97,3871.96 10220.24,3872.44 10281.21,3872.92 9924.57,3880.61 9499.57,3885.61 7964.57,3894.39 8949.57,3925.61 9150.77,3970.6 8624.57,3977.5 7964.57,4012.5 10775.57,4015.31 11033.65,4015.54 11228.8,4015.85 8951.08,4019.38 9044.57,4040.61 8104.57,4052.5 9105.77,4073.71 9514.57,4075.61 8299,4078.71 9361.99,4078.71 9952.54,4078.71 10070.65,4078.71 10188.76,4078.71 10404.57,4079.39 9439.57,4085.61 8624.57,4095.61 8374.57,4100.61 7964.57,4130.61 9314.57,4139.39 12509.12,4164.62 11624.03,4166.99 11549.18,4167.71 9135.77,4171.82 8134.57,4185.61 8474.57,4185.61 10386.94,4190.74 8299,4196.82 8371.4,4197.15 9361.99,4196.82 9952.54,4196.82 10070.65,4196.82 10188.76,4196.82 11727.93,4220.98 11547.64,4221.77 11619.09,4222.05 8624.57,4232.5 11086.46,4234.02 9314.57,4257.5 12613.72,4260.23 11385.03,4262.01 9218.34,4266.61 8099.57,4269.39 11456.18,4277.39 9139.57,4280.61 8432.74,4294.95 10730.04,4301.05 10139.64,4309.43 10064.81,4313.39 10399.24,4313.56 9361.99,4314.93 9952.54,4314.93 10536.27,4315.64 11969.43,4318.03 12242.57,4319.29 12549.4,4323.06 10988.84,4324.34 10823.72,4325.3 10909.7,4325.83 11096.88,4325.83 11189.53,4325.82 8624.57,4350.61 8079.57,4355.61 11453.44,4358.89 8463.33,4361.23 9219.57,4370.61 9314.57,4375.61 10813.35,4375.83 12609.62,4379.62 11372.88,4380.53 11102.16,4385 10914.13,4386.53 11013.73,4387.03 11176.75,4386.64 11234.34,4386.64 12500.37,4393.67 10141.94,4409.99 10040.24,4419.68 8269,4428.04 9361.99,4433.04 9952.54,4433.04 13102.08,4449.68 12978.31,4461.01 8625.22,4479.93 10454.31,4490.33 10138.63,4491.28 12818.53,4494.96 9359.57,4505.61 12972.64,4528.13 13208.86,4528.13 11451.68,4561.79 9495.17,4563.45 10808.14,4564.69 9109.57,4570.61 11016.87,4583.72 7964.57,4594.39 11224.09,4610.88 12805.92,4612.38 12501.3,4621.86 12550.65,4621.86 11453.53,4634.21 9671.57,4641.61 13208.86,4646.24 13326.97,4646.24 11318.07,4653.66 8938.27,4661.7 13128.57,4666.61 8417.11,4669.26 9361.99,4669.26 10910.91,4669.26 11015.53,4669.26 11369.87,4669.26 8489.51,4669.59 8084.57,4674.39 12807.31,4691.25 8454.25,4700 12499.5,4710.11 12553.38,4710.14 7964.57,4712.5 13086.57,4713.61 10195.32,4717.34 8886.25,4718.87 10807.6,4720.14 13012.87,4720.23 9734.57,4722.61 12215.09,4723.1 9855.76,4724.84 9973.91,4725.6 13184.57,4734.61 11104.74,4746.83 11197.11,4751.82 11013.41,4757.21 13326.97,4764.35 11315.3,4766.21 11453.53,4779.43 10030.53,4781.01 9930.71,4783.37 9827.67,4784.29 9249.17,4786.41 10807.5,4788.89 12025.41,4789.56 8084.57,4792.5 11387.57,4795.61 8624.57,4799.39 13374.49,4803.42 12952.08,4823.21 13255.8,4824.44 11453.53,4824.94 12904.08,4828.13 7964.57,4830.61 9855.25,4837.91 9974.68,4839.18 11370.06,4841.01 9575.57,4842.61 11000.57,4847.61 11097.57,4847.61 11174.57,4847.61 10907.57,4848.61 11227.57,4848.61 13181.57,4861.61 13541.65,4877.71 13013.04,4880.69 12500.2,4882.46 12736.42,4882.46 8839.57,4890.61 12019.02,4897.68 8180.89,4905.48 9248.21,4905.48 13644.71,4908.98 8084.57,4910.61 13002,4922.67 8624.57,4926.25 9626.57,4931.61 13790.35,4938.36 13913.75,4939.11 13181.32,4942.6 13110.28,4945.36 10919.94,4958 10961.57,4958.61 11160.57,4959.61 11345.57,4962.61 9355.15,4964.33 9493.64,4964.29 11474.74,4966.62 11503.95,4996.22 13917.52,5000.57 13999.57,5012.61 13110.87,5020.11 8180.89,5023.59 9125.77,5023.59 13175.78,5029.78 8624.26,5030.62 13494.57,5032.61 11207.57,5062.61 13494.57,5070.61 13122.89,5072.52 11013.57,5074.61 14000.57,5076.61 8834.96,5078.07 11205.57,5091.61 9209.57,5095.61 13071.87,5095.76 13326.57,5103.61 13531.87,5112 8206.12,5115.46 13468.57,5115.61 13240.24,5124.2 13657.57,5127.61 12962.05,5135.2 14000.57,5140.61 8299,5141.7 8889.55,5141.7 9007.66,5141.7 9125.77,5141.7 13566.46,5144.99 13301.57,5146.61 13350.57,5146.61 13403.57,5146.61 13854.57,5146.61 13900.57,5146.61 13494.57,5147.61 13728.57,5148.61 13241.78,5172.17 9435.18,5173.68 9204.57,5180.61 12418.66,5181.01 12945.44,5182.56 8614.57,5189.39 13155.14,5202.46 12456.18,5217.29 8219.57,5232.5 12956.28,5243.24 12828.05,5256.62 8299,5259.81 8831.46,5285.61 8944.57,5285.61 9047.68,5285.61 8614.57,5307.5 9339.57,5310.61 12830.81,5312.43 9428.04,5317.21 8829.57,5345.61 8942.68,5345.61 8219.57,5350.61 9045.17,5351.15 7984.57,5374.39 8180.89,5377.92 8299,5377.92 8417.11,5377.92 12314.75,5377.92 12432.86,5377.92 10631.33,5379.73 9339.57,5384.93 9427.35,5400.89 12714.04,5409.2 8614.57,5425.61 9099.57,5430.61 12790.71,5485.58 7984.57,5492.5 12314.75,5496.03 12432.86,5496.03 13115.36,5502.44 9339.57,5510.61 12900.76,5515.24 9431.5,5517.07 8804.71,5527.77 9060.59,5535.15 8944.57,5535.61 13056.2,5568.86 11859.02,5590.1 7984.57,5610.61 8771.44,5614.14 8889.55,5614.14 9007.66,5614.14 9125.77,5614.14 9243.88,5614.14 12905.3,5614.14 12998.08,5622.83 13120.55,5633.21 8109.57,5650.61 8062.78,5732.25 8535.22,5732.25 8771.44,5732.25 8889.55,5732.25 9125.77,5732.25 12905.3,5732.25 13023.41,5732.25 13227.03,5750.69 13244.28,5826.07 8076.21,5843.18 12780.53,5846.89 8535.22,5850.36 9007.66,5850.36 9125.77,5850.36 12432.86,5850.36 12550.97,5850.36 12669.08,5850.36 9237.66,5857.97 11095.21,5908.35 11213.32,5908.35 11331.43,5908.35 12080.8,5908.48 12198.91,5908.48 12317.02,5908.48 10089.92,5908.57 10208.03,5908.57 10326.14,5908.57 8062.78,5968.47 8535.22,5968.47 8771.44,5968.47 8889.55,5968.47 9007.66,5968.47 9125.77,5968.47 9243.88,5968.47 12905.3,5968.47 13023.41,5968.47 13237.8,5987.23 10497.05,5992.74 10615.16,5992.74 10733.27,5992.74 9642.7,5994.01 9760.81,5994.01 9878.92,5994.01 11655.09,5994.49 11773.2,5994.49 11891.31,5994.49
  other v2: 13398.4,3045.18 13811.49,3045.18 13398.4,3219.28 13989.37,3301.73 13102.64,3333.36 13278.91,3334.45 13536.9,3342.42 12985.58,3419.92 13989.37,3453.13 13344.57,3456.29 13536.9,3461.85 12823.26,3468.1 12997.12,3523.73 12956.75,3554.73 12819.77,3575.63 13153.11,3577.03 13344.57,3578.12 13539.79,3591.13 12451.38,3601.59 12676.31,3604.83 12974.77,3626.82 12851.16,3627.87 13077.14,3628.26 13988.83,3636.42 13186.27,3642.64 12364.87,3674.04 11225.57,3674.61 10794.57,3696.61 12696,3713.12 13713.53,3714.05 12525.69,3714.74 10676.57,3748.61 13079.84,3752.98 13310.18,3752.98 12828.45,3826.48 12689.77,3831.35 12428.36,3833.15 11081.46,3867.96 10776.49,3878.34 10678.57,3886.61 13436.22,3914.58 13235.32,3932.73 12817.91,3933.81 12485.93,3934.89 12613.53,3934.89 13107.72,3934.89 11031.47,3936.2 12980.12,3935.97 13318.2,3938.21 13835.76,3964.71 12267.06,3966.16 12817.91,3995.45 13318.2,3996.85 12611.37,3998.69 13201.44,4005.66 13008.95,4015.87 13436.82,4018.28 13793.94,4020.22 12205.78,4031.76 12267.06,4033.21 12528.93,4045.64 12670.05,4045.64 10677.57,4082.61 13868.2,4083.66 12702.49,4131.61 13268.02,4141.69 10677.57,4145.61 12822.78,4152.79 12123.29,4162.12 11875.4,4163.37 13536.21,4163.32 12967.4,4176.3 12093.38,4185.98 12221.7,4185.98 11279.73,4230.23 10925.57,4247.61 12440.44,4253.63 12510.37,4254.35 11969.38,4258.55 12047.24,4258.55 12114.04,4258.55 13800.43,4260.64 13863.87,4260.64 12229.87,4261.92 11835.19,4267.94 12823.86,4308.51 12104.43,4314.78 12438.42,4327.77 12976.05,4330.94 11742.28,4335.59 12704.12,4337.61 13222.34,4352.83 13404.01,4357.7 12439.14,4383.28 13742.16,4411.56 12692.2,4420.97 11890.25,4441.28 13781.09,4453.85 13407.25,4461.51 11311.92,4483.55 13663.82,4489.9 10287.62,4495.39 11898.21,4501.3 13590.76,4511.52 12501.75,4527.66 12553.65,4527.66 13704.67,4531.71 13590.76,4571.6 12712.98,4578.13 12271.25,4582.29 12612.95,4621.65 12230.88,4622.67 12438.64,4624.9 11571.8,4664.51 11603.57,4676.61 12712.98,4697.08 12438.64,4708.52 12614.03,4710.33 12012.56,4730.73 13444.27,4746.98 12291.21,4782.42 10724.56,4788.25 12438.64,4792.15 12498.83,4792.51 10724.56,4831.99 12550.77,4839.01 10203.57,4841.61 12438.64,4864.24 12554.61,4931.47 12304.19,4931.65 12836.76,4971.13 12499.58,4992.75 12557.74,5001.88 12525.94,5056.83 12862.72,5119.92 12713.55,5167.76 12205.77,5310.86 12548.04,5382.91
LD1: LD1.2 U6.10 | length 760.9
  Top Layer w6: U6.10@8203.01,4672.63 8203.01,4728.05 8223.97,4749.01 8299.93,4749.01 8315.93,4733.01 8499.57,4733.01 v2(8528.37,4761.81) ; LD1.2@8500.43,5052.63 8537.59,5052.63 v2(8538.77,5053.81)
  Bottom Layer w6: v2(8528.37,4761.81) 8530.37,4761.81 8558.77,4790.21 8558.77,5033.81 v2(8538.77,5053.81)
LD2: LD2.2 U6.11 | length 643.9
  Top Layer w6: U6.11@8183.32,4672.63 8183.32,4735.97 8216.77,4769.41 8312.03,4769.41 8326.03,4755.41 v2(8485.57,4755.41) ; LD2.2@8501.39,4978.53 8536.37,4943.56 v2(8536.37,4939.81)
  Bottom Layer w6: v2(8485.57,4755.41) 8536.37,4806.21 v2(8536.37,4939.81)
LD3: LD3.2 U6.12 | length 524.6
  Top Layer w6: U6.12@8163.64,4672.63 8163.64,4744.28 8207.17,4787.81 8337.17,4787.81 8349.13,4775.86 v2(8382.95,4775.86) ; v2(8467.97,4868.61) 8468.42,4868.61 LD3.2@8501.43,4901.63
  Bottom Layer w6: v2(8382.95,4775.86) 8443.61,4775.86 8467.97,4800.21 v2(8467.97,4868.61)
LD4: LD4.2 U6.19 | length 706.4
  Top Layer w6: U6.19@8104.58,4495.46 8143.22,4495.46 8153.17,4505.41 8153.17,4626.61 8141.57,4638.21 8141.57,4748.21 8196.77,4803.41 8397.57,4803.41 8413.57,4787.41 8464.77,4787.41 8501.39,4824.04 LD4.2@8501.39,4825.63
LED_G: R80.2 U4.12 | length 239.1
  Top Layer w10: R80.2@13214.26,5298.48 13214.26,5239.98 13269.56,5184.68 U4.12@13269.56,5082.28
LED_Y: R81.2 U4.13 | length 179.6
  Top Layer w10: R81.2@13156.26,5298.48 13156.26,5245.98 13210.46,5191.68 U4.13@13210.48,5141.29
M-ATLK_RX: R48.1 U6.31 | length 483.9
  Top Layer w6: U6.31@8281.76,4337.98 8281.76,4271.98 8249.46,4239.58 8249.46,4170.28 8440.46,3979.28 R48.1@8440.46,3946.58
M-ATLK_TX: R47.1 U6.30 | length 457.3
  Top Layer w6: U6.30@8262.06,4337.98 8262.06,4276.28 8234.66,4248.88 8234.66,4102.88 8366.46,3971.08 R47.1@8366.46,3946.58
M-BOOT0: J9.2 U6.44 | length 154.6
  Top Layer w6: U6.44@8439.26,4534.88 8510.66,4534.88 J9.2@8569.46,4593.68
M-NRST: C22.2 P1.4 U6.7 | length 893.3
  Top Layer w6: U6.7@8262.06,4672.68 8262.06,4619.48 v2(8272.16,4609.38) ; v2(8324.77,4579.01) 8353.97,4579.01 8382.37,4550.61 v2(8382.37,4424.61)
  Bottom Layer w6: C22.2@8273.97,4579.77 8324.01,4579.77 v2(8324.77,4579.01) ; v2(8382.37,4424.61) 8409.57,4397.41 8409.57,4068.77 P1.4@8538.16,3940.18
  Bottom Layer w10: v2(8272.16,4609.38) 8273.97,4607.57 C22.2@8273.97,4579.77
M-SWCLK: P1.3 U6.37 | length 475.2
  Top Layer w6: U6.37@8439.26,4397.04 8484.75,4397.04 v2(8504.37,4377.41)
  Bottom Layer w6: v2(8504.37,4377.41) 8504.37,4333.01 8443.17,4271.81 8443.17,4135.17 P1.3@8538.16,4040.18
M-SWDIO: P1.2 U6.34 | length 376.2
  Top Layer w6: U6.34@8340.8,4337.98 8340.76,4172.56 8373.14,4140.18 P1.2@8538.16,4140.18
M-USB_DM: R12.2 U6.32 | length 1557.9
  Top Layer w6: v2(8289.29,5431.83) 8290.08,5432.61 R12.2@8290.08,5505.16 ; v2(8290.51,4244.08) 8301.46,4255.04 U6.32@8301.46,4337.98
  Bottom Layer w6: v2(8289.29,5431.83) 8270.37,5412.9 8270.37,5061.25 8122.77,4913.65 8122.77,4321.44 8208.23,4235.98 8282.42,4235.98 v2(8290.51,4244.08)
M-USB_DP: R11.2 U6.33 | length 1610.2
  Top Layer w6: R11.2@8238.07,5504.37 8238.07,5432.9 v2(8239.61,5431.36) ; v2(8317.31,4236.99) 8321.16,4240.86 U6.33@8321.16,4337.98
  Bottom Layer w6: v2(8239.61,5431.36) 8258.37,5412.6 8258.37,5066.22 8110.77,4918.62 8110.77,4316.47 8203.26,4223.98 8304.31,4223.98 v2(8317.31,4236.99)
MDINTR: R83.2 U4.32 | length 138.6
  Top Layer w6: R83.2@12800.74,4933.58 12840.82,4933.58 12851.68,4944.44 U4.32@12934.89,4944.44
MDIO: R63.2 R72.1 U4.25 | length 193.3
  Top Layer w6: R63.2@12800.74,5123.88 v2(12828.89,5095.73) 12842.38,5082.24 U4.25@12934.89,5082.24
  Bottom Layer w6: R72.1@12798.77,5124.27 12800.35,5124.27 v2(12828.89,5095.73)
NRST: B1.1 B1.3 C40.1 CN4.7 CN7.7 J2.25 J4.3 J7.5 R46.2 U1.25 | length 7006.5
  Top Layer w6: v2(8292.66,3383.78) 8292.81,3383.93 8292.81,3663.13 8292.66,3662.98 ; v1(8292.66,3645.23) 8292.66,3662.98 ; R46.2@8292.66,3892.68 8292.66,3662.98 ; v2(8616.21,3600.97) 8632.56,3584.61 8738.57,3584.61 8828.03,3674.07 B1.3@8828.03,3728.39 B1.1@9174.49,3728.39 9185.06,3738.98 9298.26,3738.98 C40.1@9331.77,3705.97 9495.26,3705.98 9584.26,3794.98 10439.66,3794.98 10439.66,3796.08 10441.57,3797.96 ; J2.25@10529.17,3267.08 10480.26,3316.08 10480.26,3403.93 10441.57,3442.61 10441.57,3797.96 ; v2(11451.16,4391.98) 11392.84,4391.98 11322.84,4461.98 U1.25@10671.86,4462.04 10539.66,4461.98 10441.57,4363.89 10441.57,3797.96 ; v2(11605.75,4447.38) 11624.94,4466.56 J7.5@12054.81,4466.56
  Bottom Layer w6: CN7.7@8195.43,3166.63 8195.43,3286.55 v2(8292.66,3383.78) ; v1(8292.66,3645.23) 8571.94,3645.23 v2(8616.21,3600.97) ; v2(8879.21,3727.97) 8879.21,4173.95 CN4.7@8933.23,4227.98 ; J2.25@10529.17,3267.08 10579.26,3317.08 10579.26,3420.98 10627.26,3468.98 10803.36,3468.98 10839.86,3505.48 J4.3@10839.86,3565.98 ; v2(11451.16,4391.98) 11550.36,4391.98 v2(11605.75,4447.38)
OTGFS1_D+: CN1.3 CN2.A6 CN2.B6 R30.2 | length 1204.8
  Top Layer w5.98: R30.2@13542.23,3985.61 13542.66,3986.04 v2(13612.26,3986.04) 13626.45,4000.23 CN2.B6@13718.81,4000.23 ; v2(13649.57,3960.93) CN2.A6@13718.81,3960.93 13791.82,3960.93 13842.51,4011.63 13842.51,4359.63
  Top Layer w6: CN1.3@13523.5,4585.28 13558.16,4550.61 13651.52,4550.61 13842.51,4359.63
  Bottom Layer w5.98: v2(13612.26,3986.04) 13637.37,3960.93 v2(13649.57,3960.93)
OTGFS1_D-: CN1.2 CN2.A7 CN2.B7 R31.2 | length 1164.7
  Top Layer w5.98: R31.2@13541.23,3933.61 13582.57,3933.61 13590.19,3941.23 13626.39,3941.23 ; CN2.B7@13718.81,3941.23 13626.39,3941.23 ; 13830.51,4354.68 13830.51,4016.55 13794.49,3980.53 CN2.A7@13718.81,3980.53 13637.73,3980.53 13626.2,3969.01 13626.2,3941.42 13626.39,3941.23
  Top Layer w6: CN1.2@13523.5,4506.54 13552.57,4535.61 13649.57,4535.61 13830.51,4354.68
PA0: J2.34 J6.1 R19.2 U1.34 | length 3215.2
  Top Layer w6: R19.2@9332.66,3653.98 9372.02,3653.98 9391.72,3673.68 9504.96,3673.68 9601.26,3769.98 v2(10391.16,3769.98) ; U1.34@10671.86,4284.87 10592.84,4284.88 10562.26,4254.23 10562.26,3886.38 10583.26,3865.38 10583.26,3769.97 10583.26,3725.98 10692.26,3616.98 10692.26,3523.98 10717.26,3498.98 10823.26,3498.98 10929.16,3392.98 J2.34@10929.17,3367.08
  Bottom Layer w6: v2(10391.16,3769.98) v2(10583.21,3769.97) ; J2.34@10929.17,3367.08 11058.16,3495.98 11406.26,3495.98 11476.26,3565.98 J6.1@11539.86,3565.98
PA1: R84.2 RP3.4 U1.35 | length 3672.3
  Top Layer w6: R84.2@10594.63,4178.39 10594.63,4246.05 10613.76,4265.18 U1.35@10671.86,4265.19 10728.76,4265.18 10812.85,4349.28 11348.9,4349.28 11499.6,4198.61 11796.23,4198.61 11885.61,4287.99 12444.09,4287.99 v2(12525.65,4369.56) ; v2(12505.53,5231.05) 12536.94,5262.48 12732.62,5262.48 12878.11,5407.98 12990.26,5407.98 12999.96,5398.28 RP3.4@12999.96,5361.98
  Bottom Layer w6: v2(12505.53,5231.05) 12481.57,5207.09 12481.57,5056.9 12525.62,5012.85 v2@12525.62,4369.59
PA1_E: J2.35 J6.2 R84.1 | length 1968.1
  Top Layer w6: R84.1@10594.63,4119.07 10594.63,3878.41 10611.56,3861.48 10611.56,3728.68 10709.66,3630.58 10867.66,3630.58 10896.26,3601.98 10896.26,3525.98 10978.26,3443.98 10978.26,3318.08 J2.35@11029.17,3267.08
  Bottom Layer w6: J2.35@11029.17,3267.08 11078.26,3315.98 11078.26,3449.98 11102.26,3473.98 11600.16,3473.98 11639.86,3513.58 J6.2@11639.86,3565.98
